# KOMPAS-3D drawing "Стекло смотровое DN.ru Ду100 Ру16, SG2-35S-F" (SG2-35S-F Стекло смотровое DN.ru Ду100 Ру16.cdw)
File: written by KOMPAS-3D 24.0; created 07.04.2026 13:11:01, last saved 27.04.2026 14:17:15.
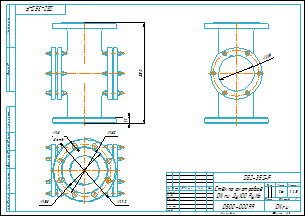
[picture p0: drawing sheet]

Document properties: Автор: Main; Форматы листов документа: A3; Полное имя файла: SG2-35S-F Стекло смотровое DN.ru Ду100 Ру16.m3d; Масса: 26; Наименование: Стекло смотровое DN.ru Ду100 Ру16; Количество листов документа: 1; Примечание: D500-00099

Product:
- Body: Тело 1  | qty 1
    Масса: 25.876303
- Part/product: Стекло смотровое DN.ru Ду100 Ру16  | designation SG2-35S-F
    Масса: 26
    Раздел спецификации: Прочие изделия
    Примечание: D500-00099

Views: Проекционный вид 3
Referenced files in D:\DN.ru Аутсерс\Стекло смотровое DN.ru\Стекло смотровое DN.ru SG2-34G-F тип В ГОСТ 21836-2021 Ду100 Ру16, углеродистая сталь, фланцевое\: SG2-34G-F тип В Стекло смотровое DN.ru Ду100 Ру16.m3d, SG2-34G-F тип ВСтекло смотровое DN.ru Ду100 Ру16.cdw
Referenced files in D:\DN.ru Аутсорс\Стекло смотровое DN.ru\SG2-35S-F Стекло смотровое DN.ru Ду100 Ру16\: SG2-35S-F Стекло смотровое DN.ru Ду100 Ру16.m3d
Referenced files in D:\DN.ru Аутсерс\Стекло смотровое DN.ru\SG2-35S-F Стекло смотровое DN.ru Ду100 Ру16\: SG2-35S-F Стекло смотровое DN.ru Ду100 Ру16.m3d
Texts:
  SG2-35S-F
  Стекло смотровое
  DN.ru Ду100 Ру16
  Стекло смотровое DN.ru Ду100 Ру16
  SG2-35S-F Стекло смотровое DN.ru Ду100 Ру16
Dimensions and other numbers on the sheet: 0; 3; 4; 125; 1:2,5; 1; 2; 26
